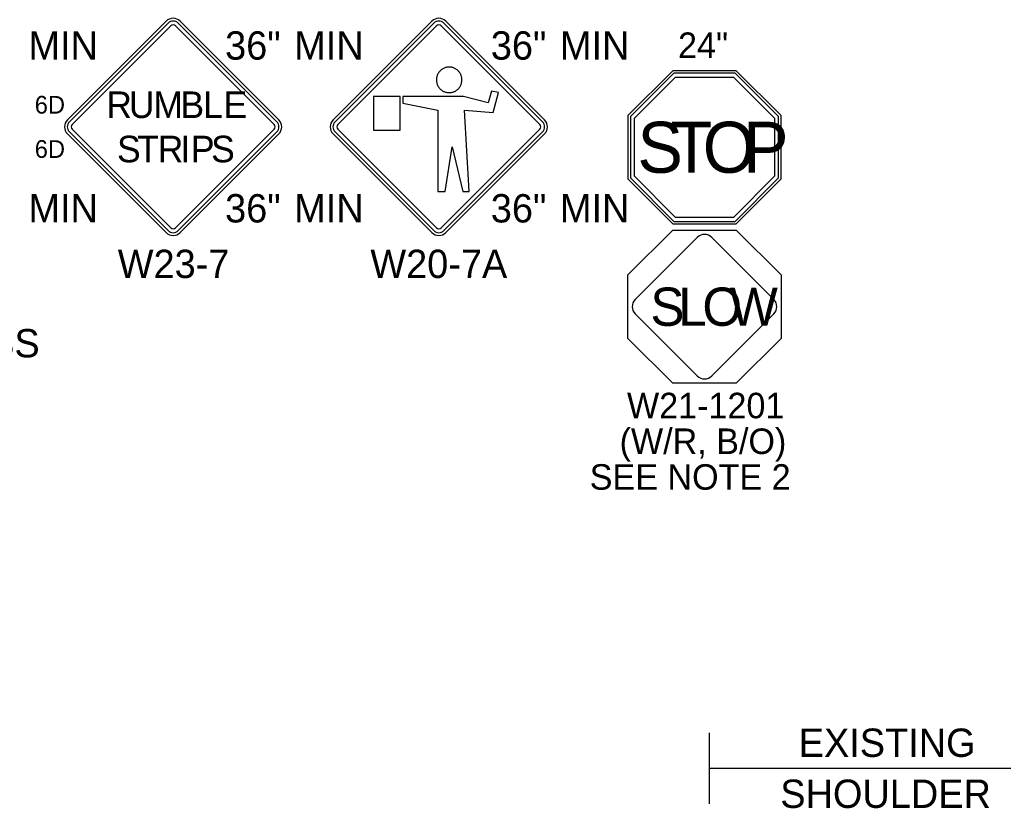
# Model space of a CAD drawing. Extents: x 99999.1 to 100095.7, y 99995 to 100010.7.
# Drawn here: x 100042.344 to 100045.12, y 100003.262 to 100005.488 of the extents above; entities that cross this region are included whole.
import ezdxf

# ---------------------------------------------------------------- set-up
doc = ezdxf.new("R2010")
doc.units = 0
doc.layers.add('TR_SN_ConstructionSigns', color=7, linetype='Continuous')
doc.layers.add('TR_WZ_WorkZoneDetails', color=7, linetype='Continuous')

msp = doc.modelspace()

# ---------------------------------------------------------------- linework, layer by layer
at = {"layer": 'TR_SN_ConstructionSigns'}
for p, q in [((100042.7568, 100005.4841), (100042.4783, 100005.2057)), ((100042.7623, 100005.4786), (100042.4839, 100005.2001)), ((100042.4916, 100005.1924), (100042.77, 100005.4708)), ((100042.7833, 100005.4708), (100043.0617, 100005.1924)), ((100043.0694, 100005.2001), (100042.791, 100005.4786)), ((100043.075, 100005.2057), (100042.7965, 100005.4841)), ((100043.5068, 100005.4841), (100043.2283, 100005.2057)), ((100043.5123, 100005.4786), (100043.2339, 100005.2001)), ((100043.2416, 100005.1924), (100043.52, 100005.4708)), ((100043.5333, 100005.4708), (100043.8117, 100005.1924)), ((100043.8194, 100005.2001), (100043.541, 100005.4786)), ((100043.825, 100005.2057), (100043.5465, 100005.4841)), ((100043.5216, 100005.3298), (100043.5211, 100005.328)), ((100043.5223, 100005.3316), (100043.5216, 100005.3298)), ((100043.523, 100005.3334), (100043.5223, 100005.3316)), ((100043.5238, 100005.3351), (100043.523, 100005.3334)), ((100043.5248, 100005.3368), (100043.5238, 100005.3351)), ((100043.5258, 100005.3385), (100043.5248, 100005.3368)), ((100043.5269, 100005.34), (100043.5258, 100005.3385)), ((100043.5281, 100005.3415), (100043.5269, 100005.34)), ((100043.5293, 100005.343), (100043.5281, 100005.3415)), ((100043.5307, 100005.3443), (100043.5293, 100005.343)), ((100043.5321, 100005.3456), (100043.5307, 100005.3443)), ((100043.5336, 100005.3468), (100043.5321, 100005.3456)), ((100043.5351, 100005.348), (100043.5336, 100005.3468)), ((100043.5367, 100005.349), (100043.5351, 100005.348)), ((100043.5384, 100005.35), (100043.5367, 100005.349)), ((100043.5401, 100005.3509), (100043.5384, 100005.35)), ((100043.5418, 100005.3517), (100043.5401, 100005.3509)), ((100043.5436, 100005.3524), (100043.5418, 100005.3517)), ((100043.5454, 100005.353), (100043.5436, 100005.3524)), ((100043.5473, 100005.3535), (100043.5454, 100005.353)), ((100043.5492, 100005.3539), (100043.5473, 100005.3535)), ((100043.5511, 100005.3542), (100043.5492, 100005.3539)), ((100043.5529, 100005.3544), (100043.5511, 100005.3542)), ((100043.5549, 100005.3545), (100043.5529, 100005.3544)), ((100043.5568, 100005.3545), (100043.5549, 100005.3545)), ((100043.5587, 100005.3544), (100043.5568, 100005.3545)), ((100043.5606, 100005.3542), (100043.5587, 100005.3544)), ((100043.5625, 100005.3539), (100043.5606, 100005.3542)), ((100043.5644, 100005.3535), (100043.5625, 100005.3539)), ((100043.5662, 100005.353), (100043.5644, 100005.3535)), ((100043.5681, 100005.3524), (100043.5662, 100005.353)), ((100043.5698, 100005.3517), (100043.5681, 100005.3524)), ((100043.5716, 100005.3509), (100043.5698, 100005.3517)), ((100043.5733, 100005.35), (100043.5716, 100005.3509)), ((100043.575, 100005.349), (100043.5733, 100005.35)), ((100043.5765, 100005.348), (100043.575, 100005.349)), ((100043.5781, 100005.3468), (100043.5765, 100005.348)), ((100043.5795, 100005.3456), (100043.5781, 100005.3468)), ((100043.581, 100005.3443), (100043.5795, 100005.3456)), ((100043.5823, 100005.343), (100043.581, 100005.3443)), ((100043.5835, 100005.3415), (100043.5823, 100005.343)), ((100043.5847, 100005.34), (100043.5835, 100005.3415)), ((100043.5858, 100005.3385), (100043.5847, 100005.34)), ((100043.5868, 100005.3368), (100043.5858, 100005.3385)), ((100043.5878, 100005.3351), (100043.5868, 100005.3368)), ((100043.5886, 100005.3334), (100043.5878, 100005.3351)), ((100043.5893, 100005.3316), (100043.5886, 100005.3334)), ((100043.59, 100005.3298), (100043.5893, 100005.3316)), ((100043.5906, 100005.328), (100043.59, 100005.3298)), ((100044.1871, 100005.3443), (100044.0606, 100005.2178)), ((100044.1899, 100005.3376), (100044.0673, 100005.215)), ((100044.366, 100005.3443), (100044.1871, 100005.3443)), ((100044.3632, 100005.3376), (100044.1899, 100005.3376)), ((100044.4858, 100005.215), (100044.3632, 100005.3376)), ((100044.4926, 100005.2178), (100044.366, 100005.3443)), ((100043.52, 100005.3223), (100043.5198, 100005.3204)), ((100043.5198, 100005.3204), (100043.5198, 100005.3185)), ((100043.5198, 100005.3185), (100043.5198, 100005.3166)), ((100043.5198, 100005.3166), (100043.52, 100005.3147)), ((100043.5203, 100005.3243), (100043.52, 100005.3223)), ((100043.52, 100005.3147), (100043.5203, 100005.3128)), ((100043.5206, 100005.3261), (100043.5203, 100005.3243)), ((100043.5203, 100005.3128), (100043.5206, 100005.3109)), ((100043.5211, 100005.328), (100043.5206, 100005.3261)), ((100043.5206, 100005.3109), (100043.5211, 100005.309)), ((100043.5211, 100005.309), (100043.5216, 100005.3072)), ((100043.5216, 100005.3072), (100043.5223, 100005.3054)), ((100043.5223, 100005.3054), (100043.523, 100005.3036)), ((100043.523, 100005.3036), (100043.5238, 100005.3019)), ((100043.5238, 100005.3019), (100043.5248, 100005.3002)), ((100043.5868, 100005.3002), (100043.5878, 100005.3019)), ((100043.5878, 100005.3019), (100043.5886, 100005.3036)), ((100043.5886, 100005.3036), (100043.5893, 100005.3054)), ((100043.5893, 100005.3054), (100043.59, 100005.3072)), ((100043.59, 100005.3072), (100043.5906, 100005.309)), ((100043.591, 100005.3261), (100043.5906, 100005.328)), ((100043.5906, 100005.309), (100043.591, 100005.3109)), ((100043.5914, 100005.3243), (100043.591, 100005.3261)), ((100043.591, 100005.3109), (100043.5914, 100005.3128)), ((100043.5917, 100005.3223), (100043.5914, 100005.3243)), ((100043.5914, 100005.3128), (100043.5917, 100005.3147)), ((100043.5918, 100005.3204), (100043.5917, 100005.3223)), ((100043.5917, 100005.3147), (100043.5918, 100005.3166)), ((100043.5918, 100005.3185), (100043.5918, 100005.3204)), ((100043.5918, 100005.3166), (100043.5918, 100005.3185)), ((100044.0786, 100005.2104), (100044.1945, 100005.3263)), ((100044.1945, 100005.3263), (100044.3586, 100005.3263)), ((100044.3586, 100005.3263), (100044.4746, 100005.2104)), ((100043.5248, 100005.3002), (100043.5258, 100005.2986)), ((100043.5258, 100005.2986), (100043.5269, 100005.297)), ((100043.5269, 100005.297), (100043.5281, 100005.2955)), ((100043.5281, 100005.2955), (100043.5293, 100005.2941)), ((100043.5293, 100005.2941), (100043.5307, 100005.2927)), ((100043.5307, 100005.2927), (100043.5321, 100005.2914)), ((100043.5321, 100005.2914), (100043.5336, 100005.2902)), ((100043.5336, 100005.2902), (100043.5351, 100005.289)), ((100043.5351, 100005.289), (100043.5367, 100005.288)), ((100043.5367, 100005.288), (100043.5384, 100005.287)), ((100043.5384, 100005.287), (100043.5401, 100005.2861)), ((100043.5401, 100005.2861), (100043.5418, 100005.2853)), ((100043.5418, 100005.2853), (100043.5436, 100005.2846)), ((100043.5436, 100005.2846), (100043.5454, 100005.284)), ((100043.5454, 100005.284), (100043.5473, 100005.2835)), ((100043.5473, 100005.2835), (100043.5492, 100005.2831)), ((100043.5492, 100005.2831), (100043.5511, 100005.2828)), ((100043.5511, 100005.2828), (100043.5529, 100005.2826)), ((100043.5529, 100005.2826), (100043.5549, 100005.2825)), ((100043.5549, 100005.2825), (100043.5568, 100005.2825)), ((100043.5568, 100005.2825), (100043.5587, 100005.2826)), ((100043.5587, 100005.2826), (100043.5606, 100005.2828)), ((100043.5606, 100005.2828), (100043.5625, 100005.2831)), ((100043.5625, 100005.2831), (100043.5644, 100005.2835)), ((100043.5644, 100005.2835), (100043.5662, 100005.284)), ((100043.5662, 100005.284), (100043.5681, 100005.2846)), ((100043.5681, 100005.2846), (100043.5698, 100005.2853)), ((100043.5698, 100005.2853), (100043.5716, 100005.2861)), ((100043.5716, 100005.2861), (100043.5733, 100005.287)), ((100043.5733, 100005.287), (100043.575, 100005.288)), ((100043.575, 100005.288), (100043.5765, 100005.289)), ((100043.5765, 100005.289), (100043.5781, 100005.2902)), ((100043.5781, 100005.2902), (100043.5795, 100005.2914)), ((100043.5795, 100005.2914), (100043.581, 100005.2927)), ((100043.581, 100005.2927), (100043.5823, 100005.2941)), ((100043.5823, 100005.2941), (100043.5835, 100005.2955)), ((100043.5835, 100005.2955), (100043.5847, 100005.297)), ((100043.5847, 100005.297), (100043.5858, 100005.2986)), ((100043.5858, 100005.2986), (100043.5868, 100005.3002)), ((100043.6753, 100005.2869), (100043.6656, 100005.2541)), ((100043.6953, 100005.2833), (100043.6753, 100005.2869)), ((100043.6803, 100005.2265), (100043.6953, 100005.2833)), ((100043.3424, 100005.2712), (100043.3424, 100005.1765)), ((100043.4177, 100005.2712), (100043.3424, 100005.2712)), ((100043.4177, 100005.1765), (100043.4177, 100005.2712)), ((100043.5961, 100005.2712), (100043.4247, 100005.2712)), ((100043.4247, 100005.2712), (100043.4247, 100005.2531)), ((100043.4247, 100005.2531), (100043.5242, 100005.2333)), ((100043.6656, 100005.2541), (100043.5961, 100005.2712)), ((100043.5242, 100005.2333), (100043.5242, 100005.003)), ((100043.6124, 100005.003), (100043.5993, 100005.2334)), ((100043.5993, 100005.2334), (100043.6803, 100005.2265)), ((100044.0606, 100005.2178), (100044.0606, 100005.0389)), ((100044.0673, 100005.215), (100044.0673, 100005.0417)), ((100044.0786, 100005.0463), (100044.0786, 100005.2104)), ((100044.4746, 100005.2104), (100044.4746, 100005.0463)), ((100044.4858, 100005.0417), (100044.4858, 100005.215)), ((100044.4926, 100005.0389), (100044.4926, 100005.2178)), ((100042.4783, 100005.1659), (100042.7568, 100004.8875)), ((100042.4839, 100005.1714), (100042.7623, 100004.893)), ((100042.77, 100004.9007), (100042.4916, 100005.1792)), ((100043.0617, 100005.1792), (100042.7833, 100004.9007)), ((100042.791, 100004.893), (100043.0694, 100005.1714)), ((100042.7965, 100004.8875), (100043.075, 100005.1659)), ((100043.2283, 100005.1659), (100043.5068, 100004.8875)), ((100043.2339, 100005.1714), (100043.5123, 100004.893)), ((100043.52, 100004.9007), (100043.2416, 100005.1792)), ((100043.3424, 100005.1765), (100043.4177, 100005.1765)), ((100043.8117, 100005.1792), (100043.5333, 100004.9007)), ((100043.541, 100004.893), (100043.8194, 100005.1714)), ((100043.5465, 100004.8875), (100043.825, 100005.1659)), ((100043.5444, 100005.003), (100043.5641, 100005.1297)), ((100043.5641, 100005.1297), (100043.5944, 100005.003)), ((100044.0606, 100005.0389), (100044.1871, 100004.9123)), ((100044.0673, 100005.0417), (100044.1899, 100004.9191)), ((100044.1945, 100004.9303), (100044.0786, 100005.0463)), ((100044.4746, 100005.0463), (100044.3586, 100004.9303)), ((100044.3632, 100004.9191), (100044.4858, 100005.0417)), ((100044.366, 100004.9123), (100044.4926, 100005.0389)), ((100043.5242, 100005.003), (100043.5444, 100005.003)), ((100043.5944, 100005.003), (100043.6124, 100005.003)), ((100044.1899, 100004.9191), (100044.3632, 100004.9191)), ((100044.3586, 100004.9303), (100044.1945, 100004.9303)), ((100044.1871, 100004.9123), (100044.366, 100004.9123)), ((100044.2562, 100004.874), (100044.0809, 100004.6987)), ((100044.4722, 100004.6987), (100044.2969, 100004.874)), ((100044.0809, 100004.658), (100044.2562, 100004.4827)), ((100044.2969, 100004.4827), (100044.4722, 100004.658))]:
    msp.add_line(p, q, dxfattribs=at)
msp.add_lwpolyline([(100044.4926, 100004.7678), (100044.4926, 100004.5889), (100044.366, 100004.4623), (100044.1871, 100004.4623), (100044.0606, 100004.5889), (100044.0606, 100004.7678), (100044.1871, 100004.8943), (100044.366, 100004.8943)], close=True, dxfattribs=at)
for centre, radius, start, end in [((100042.7767, 100005.4642), 0.0281, 45, 135), ((100042.7767, 100005.4642), 0.0203, 45, 135), ((100042.7767, 100005.4642), 0.00937, 45, 135), ((100043.5267, 100005.4642), 0.0281, 45, 135), ((100043.5267, 100005.4642), 0.0203, 45, 135), ((100043.5267, 100005.4642), 0.00937, 45, 135), ((100042.4982, 100005.1858), 0.0281, 135, 225), ((100042.4982, 100005.1858), 0.0203, 135, 225), ((100042.4982, 100005.1858), 0.00937, 135, 225), ((100043.0551, 100005.1858), 0.00937, 315, 45), ((100043.0551, 100005.1858), 0.0203, 315, 45), ((100043.0551, 100005.1858), 0.0281, 315, 45), ((100043.2482, 100005.1858), 0.0281, 135, 225), ((100043.2482, 100005.1858), 0.0203, 135, 225), ((100043.2482, 100005.1858), 0.00937, 135, 225), ((100043.8051, 100005.1858), 0.00937, 315, 45), ((100043.8051, 100005.1858), 0.0203, 315, 45), ((100043.8051, 100005.1858), 0.0281, 315, 45), ((100042.7767, 100004.9074), 0.0281, 225, 315), ((100042.7767, 100004.9074), 0.0203, 225, 315), ((100042.7767, 100004.9074), 0.00937, 225, 315), ((100043.5267, 100004.9074), 0.0281, 225, 315), ((100043.5267, 100004.9074), 0.0203, 225, 315), ((100043.5267, 100004.9074), 0.00937, 225, 315), ((100044.2766, 100004.8536), 0.0288, 45, 135), ((100044.1013, 100004.6783), 0.0288, 135, 225), ((100044.4518, 100004.6783), 0.0288, 315, 45), ((100044.2766, 100004.5031), 0.0288, 225, 315)]:
    msp.add_arc(centre, radius, start, end, dxfattribs=at)
at = {"layer": 'TR_WZ_WorkZoneDetails'}
for p, q in [((100044.2907, 100003.2755), (100044.2907, 100003.4755)), ((100044.2907, 100003.3755), (100045.2907, 100003.3755))]:
    msp.add_line(p, q, dxfattribs=at)

# ---------------------------------------------------------------- texts
at = {"layer": 'TR_SN_ConstructionSigns'}
for s, height, p in [('MIN', 0.08, (100042.3684, 100005.3756)), ('36"', 0.08, (100042.9234, 100005.3756)), ('MIN', 0.08, (100043.1184, 100005.3756)), ('36"', 0.08, (100043.6734, 100005.3756)), ('MIN', 0.08, (100043.8684, 100005.3756)), ('36"', 0.08, (100042.9234, 100004.916)), ('36"', 0.08, (100043.6734, 100004.916)), ('MIN', 0.08, (100042.3684, 100004.916)), ('MIN', 0.08, (100043.1184, 100004.916)), ('MIN', 0.08, (100043.8684, 100004.916)), ('W23-7', 0.08, (100042.6204, 100004.7592)), ('W20-7A', 0.08, (100043.3334, 100004.7592)), ('40 MPH OR LESS', 0.08, (100041.5202, 100004.5352)), ('W21-1201', 0.072, (100044.0578, 100004.3633)), ('(W/R, B/O)', 0.072, (100044.0369, 100004.2625)), ('SEE NOTE 2', 0.072, (100043.9526, 100004.1617))]:
    msp.add_text(s, height=height, rotation=360, dxfattribs=at).set_placement(p)
for s, height, p in [('24"', 0.072, (100044.2019, 100005.3803)), ('R', 0.075, (100042.588, 100005.2108)), ('U', 0.075, (100042.6518, 100005.2108)), ('M', 0.075, (100042.7208, 100005.2108)), ('B', 0.075, (100042.7973, 100005.2108)), ('L', 0.075, (100042.861, 100005.2108)), ('E', 0.075, (100042.9188, 100005.2108)), ('6D', 0.05, (100042.3861, 100005.2233)), ('S', 0.144, (100044.0872, 100005.0563)), ('T', 0.144, (100044.1808, 100005.0563)), ('O', 0.144, (100044.2715, 100005.0563)), ('P', 0.144, (100044.3853, 100005.0563)), ('6D', 0.05, (100042.3861, 100005.0983)), ('S', 0.075, (100042.6184, 100005.0858)), ('T', 0.075, (100042.6754, 100005.0858)), ('R', 0.075, (100042.7332, 100005.0858)), ('I', 0.075, (100042.7969, 100005.0858)), ('P', 0.075, (100042.8269, 100005.0858)), ('S', 0.075, (100042.8839, 100005.0858)), ('S', 0.108, (100044.1238, 100004.6243)), ('L', 0.108, (100044.2026, 100004.6243)), ('O', 0.108, (100044.2706, 100004.6243)), ('W', 0.108, (100044.3473, 100004.6243))]:
    msp.add_text(s, height=height, dxfattribs=at).set_placement(p)
at = {"layer": 'TR_WZ_WorkZoneDetails'}
for s, p in [('EXISTING', (100044.5424, 100003.4075)), ('SHOULDER', (100044.4905, 100003.2635))]:
    msp.add_text(s, height=0.08, rotation=360, dxfattribs=at).set_placement(p)

doc.saveas('drawing.dxf')
